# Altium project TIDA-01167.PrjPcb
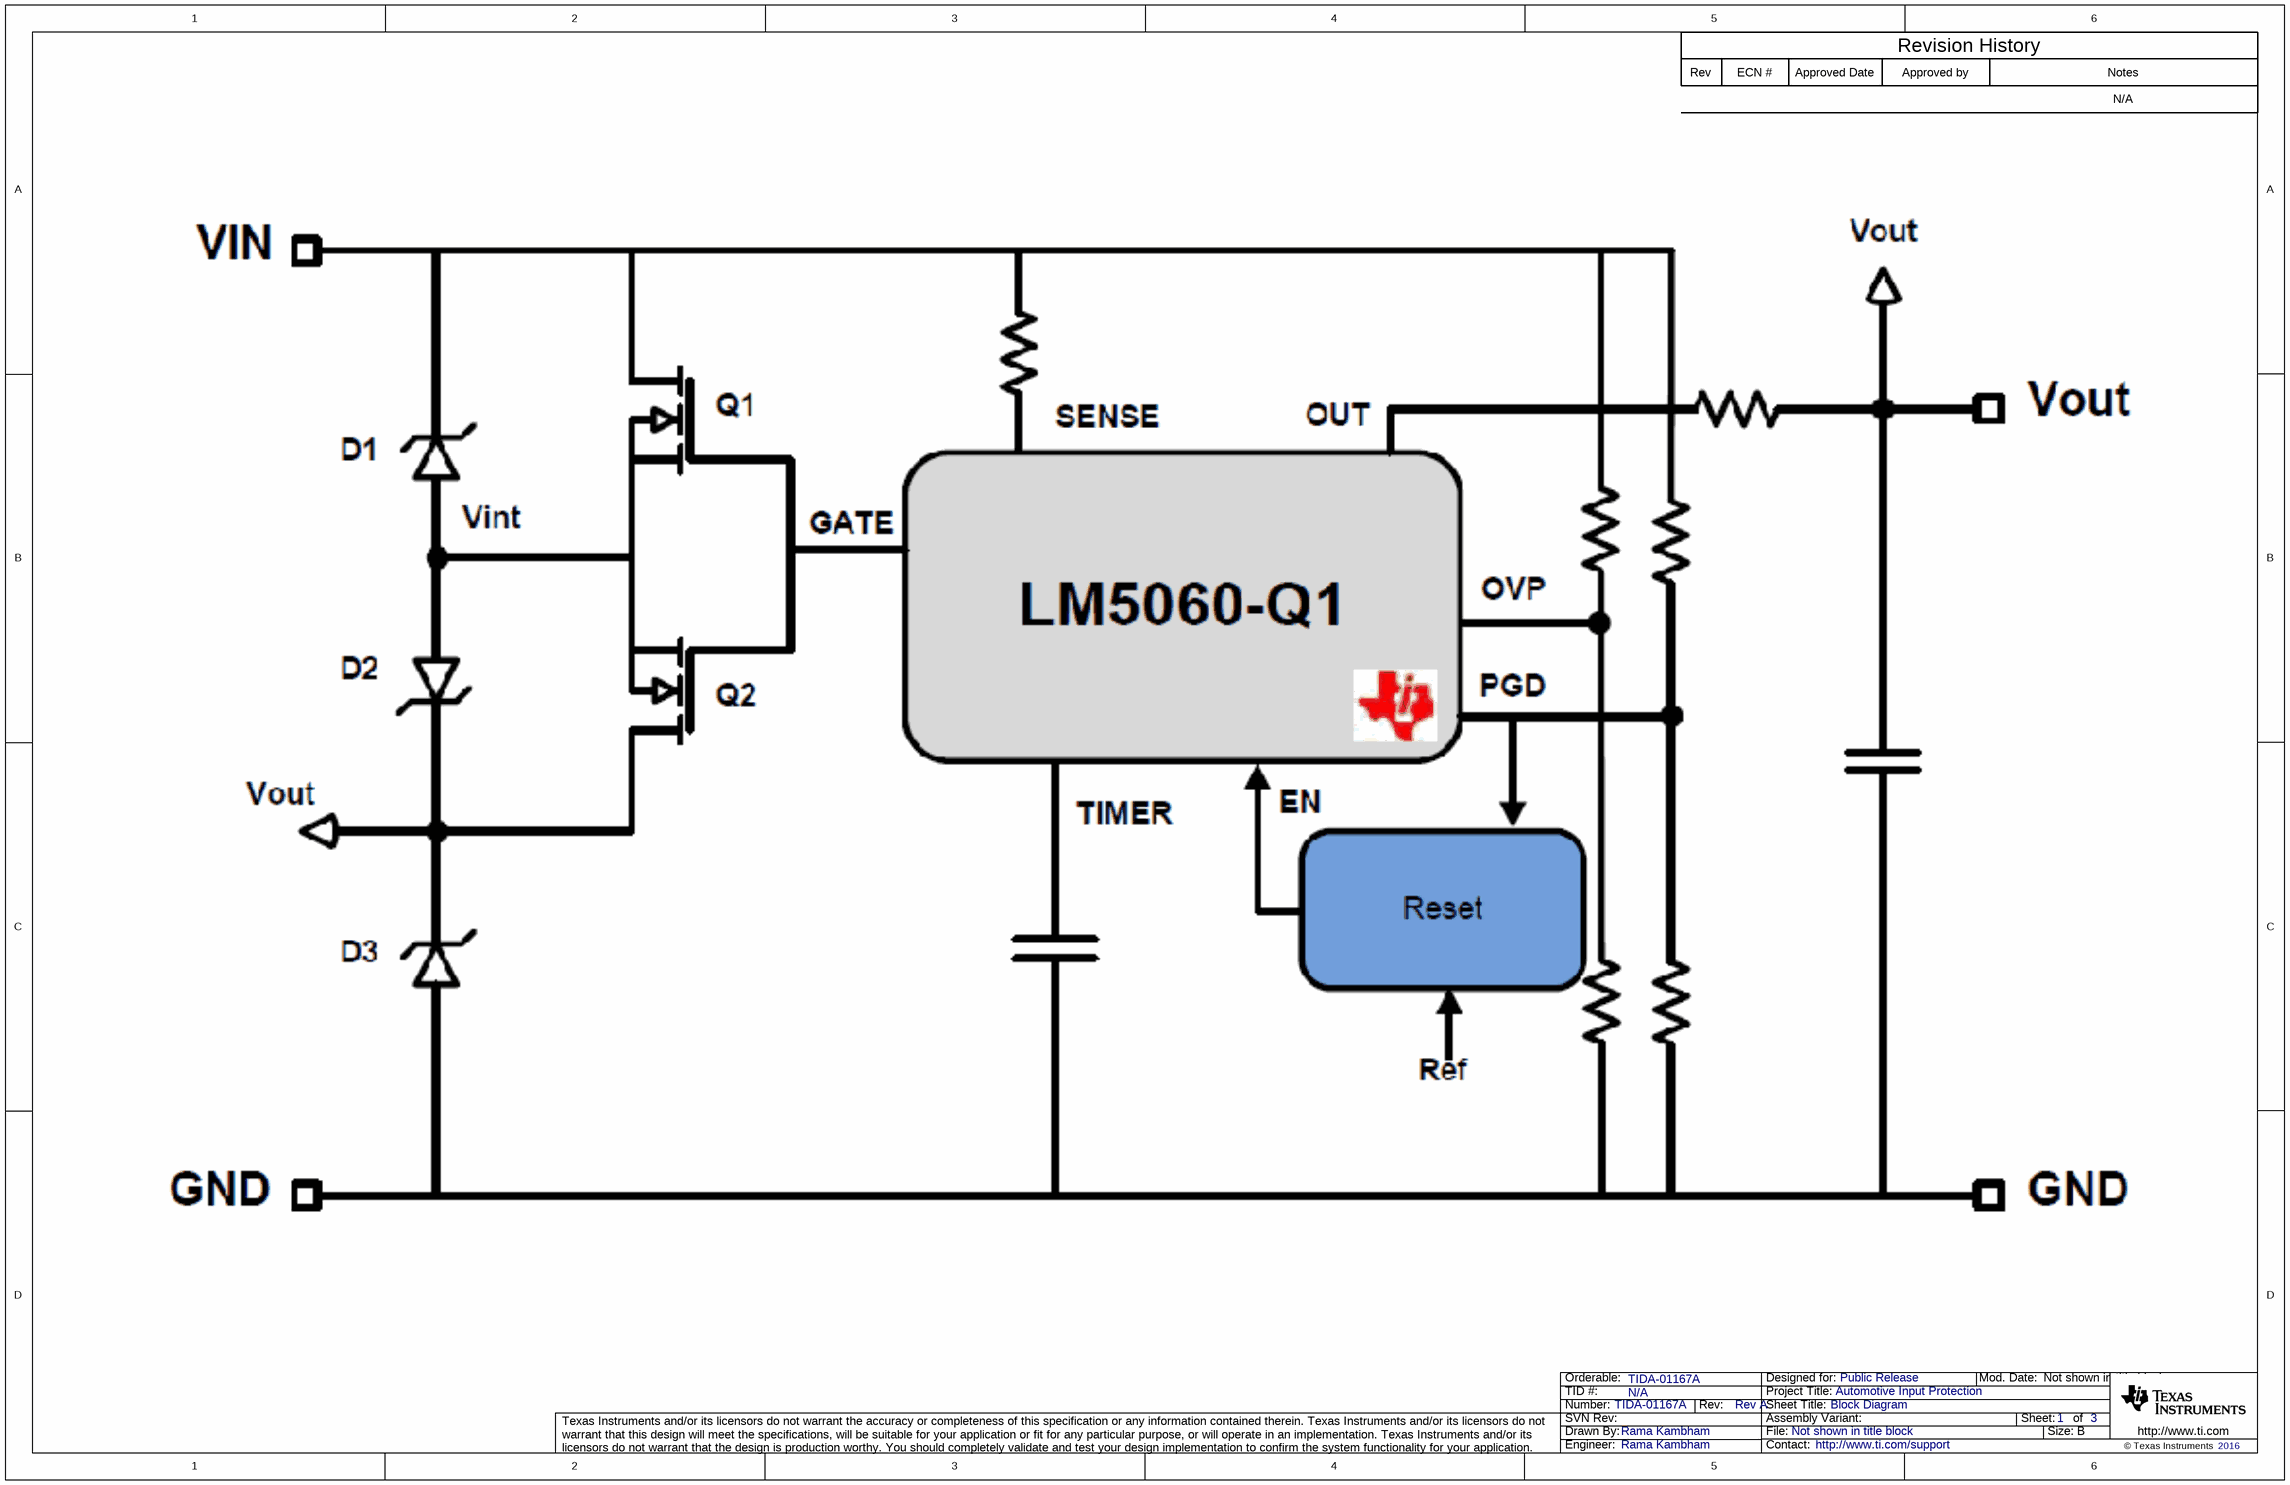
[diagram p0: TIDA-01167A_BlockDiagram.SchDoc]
CopyrightYear: 2016; EVM_orderable: TIDA-01167A; PCB_Layout: Rama Kambham; PCB_Rev: Rev A; PRJ_Customer: Public Release; PRJ_Engineer: Rama Kambham; PRJ_Number: TIDA-01167A; PRJ_Title: Automotive Input Protection; SCH_Rev: Rev A; TechSupport: http://www.ti.com/support; TID: N/A
3 sheets, 66 parts. Net scope: global (net labels, ports and power ports of the same name join across sheets).
Board file: TIDA-01167A_PCB.PcbDoc
Sheets:
  TIDA-01167A_BlockDiagram.SchDoc
  TIDA-01167A_AutomotiveInputProtection.SchDoc
  TIDA-01167A_Hardware.SchDoc

## Sheet TIDA-01167A_BlockDiagram.SchDoc: Block Diagram
size 431 x 279 mm; Date: Not shown in title block; ApprovedBy: Not shown in title block; CheckedBy: Not shown in title block; Author: Not shown in title block; CompanyName: Not shown in title block; DrawnBy: Rama Kambham; Engineer: Rama Kambham; Organization: Not shown in title block; Address1: Not shown in title block; Address2: Not shown in title block; Address3: Not shown in title block; Address4: Not shown in title block; DocumentNumber: 1; Revision: Use project parameter SCH_Rev; SheetNumber: 1; SheetTotal: 3; PageSetup: Record=PageOptions¦CenterHorizontal=True¦CenterVertical=True¦PrintScale=0.62¦XCorrection=1.00¦YCorrection=1.00¦PrintKind=0¦BorderSize=5000000¦LeftOffset=0¦BottomOffset=0¦Orientation=2¦PaperLength=1000¦PaperWidth=1000¦Scale=100¦PaperSource=15¦PrintQuality=600¦MediaType=1¦DitherType=10¦PrintScaleMode=1¦PaperKind=Letter

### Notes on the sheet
- Rev
- ECN #
- Approved Date
- Approved by
- Revision History
- Notes
- N/A

## Sheet TIDA-01167A_AutomotiveInputProtection.SchDoc: Schematic
size 431 x 279 mm; VersionControl_RevNumber: 1; Date: Not shown in title block; ApprovedBy: Not shown in title block; CheckedBy: Rama Kambham; Author: Rama Kambham; CompanyName: Not shown in title block; DrawnBy: Rama Kambham; Engineer: Rama Kambham; Organization: Not shown in title block; Address1: Not shown in title block; Address2: Not shown in title block; Address3: Not shown in title block; Address4: Not shown in title block; DocumentNumber: 1; Revision: Use project parameter SCH_Rev; SheetNumber: 2; SheetTotal: 3; PageSetup: Record=PageOptions¦CenterHorizontal=True¦CenterVertical=True¦PrintScale=0.64¦XCorrection=1.00¦YCorrection=1.00¦PrintKind=0¦BorderSize=5000000¦LeftOffset=0¦BottomOffset=0¦Orientation=2¦PaperLength=1000¦PaperWidth=1000¦Scale=100¦PaperSource=15¦PrintQuality=600¦MediaType=1¦DitherType=10¦PrintScaleMode=1¦PaperKind=8 1/2x11¦PaperIndex=1; EVM_orderable: TIDA-01167A
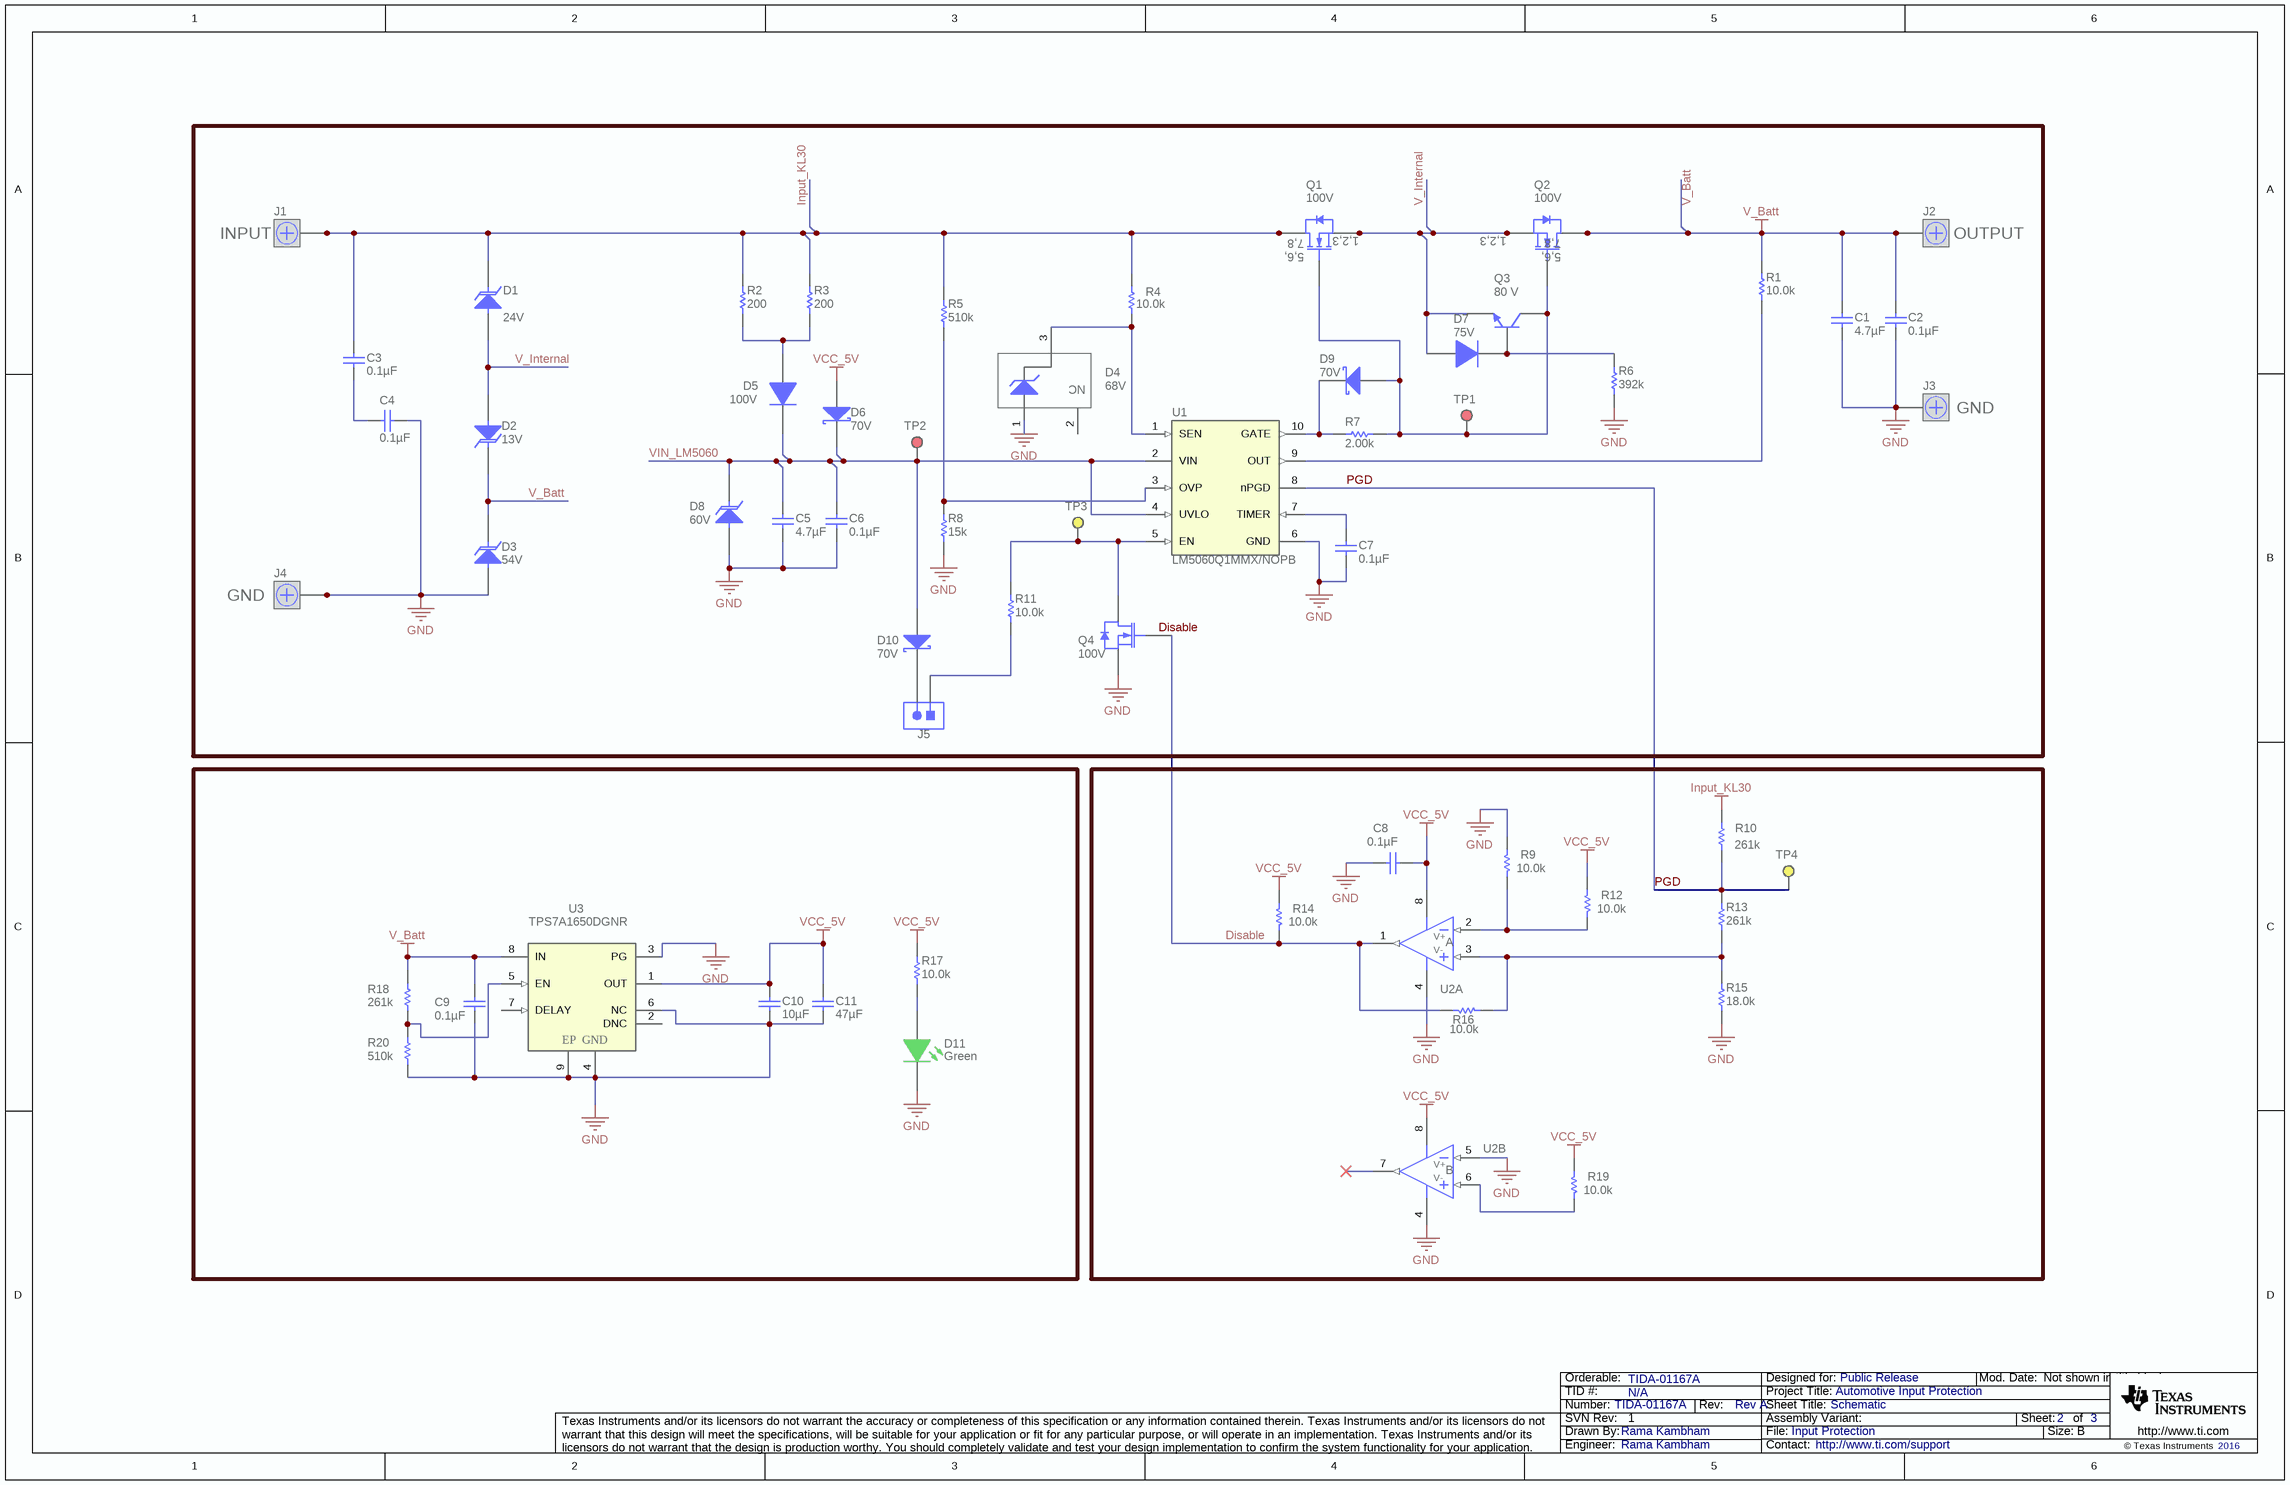
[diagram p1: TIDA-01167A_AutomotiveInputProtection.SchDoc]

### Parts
C1  ValueDisplayed: 4.7µF  [1210_270]  (hidden comment: GRM32ER71K475KE14L)
C2  ValueDisplayed: 0.1µF  [0603]  (hidden comment: GRM188R72A104KA35J)
C3  ValueDisplayed: 0.1µF  [1206]  (hidden comment: VJ1206Y104KBBAT4X)
C4  ValueDisplayed: 0.1µF  [1206]  (hidden comment: VJ1206Y104KBBAT4X)
C5  ValueDisplayed: 4.7µF  [1210_270L]  (hidden comment: GRM32ER71K475KE14L)
C6  ValueDisplayed: 0.1µF  [1206L]  (hidden comment: VJ1206Y104KBBAT4X)
C7  ValueDisplayed: 0.1µF  [0603S]  (hidden comment: GRM188R71H104KA93D)
C8  ValueDisplayed: 0.1µF  [0402]  (hidden comment: GRM155R71E104KE14D)
C9  ValueDisplayed: 0.1µF  [0603L]  (hidden comment: GRM188R72A104KA35J)
C10  ValueDisplayed: 10µF  [0805L]  (hidden comment: GRM219R61E106MA12)
C11  ValueDisplayed: 47µF  [1206_180]  (hidden comment: GRM31CR61A476KE15L)
D1  value 24V  [SMC]  (hidden comment: 5.0SMDJ24A)
D2  value 13V  [SOD-123W]  (hidden comment: PTVS13VS1UR,115)
D3  value 54V  [SMC]  (hidden comment: 5.0SMDJ54A)
D4  value 68V  [SOT-23L]  (hidden comment: BZX84C68LT1G)
D5  value 100V  [sod-323]  (hidden comment: BAS316,115)
D6  value 70V  [sod-323]  (hidden comment: 1N5711WS-7-F)
D7  value 75V  [sod-323]  (hidden comment: 1N4448WX-TP)
D8  value 60V  [SMA]  (hidden comment: SMAJ60A)
D9  value 70V  [SOD-323]  (hidden comment: BAS 170W E6327)
D10  value 70V  [sod-323]  (hidden comment: 1N5711WS-7-F)
D11  value Green  [LNJx37x8_Green]  (hidden comment: LNJ337W83RA)
J1  7693  [7693]  (value not drawn)
J2  7693  [7693]  (value not drawn)
J3  7693  [7693]  (value not drawn)
J4  7693  [7693]  (value not drawn)
J5  HTSW-102-07-G-S  [Samtec_HTSW-102-07-G-S]  (value not drawn)
Q1  value 100V  [TRANS_NexFET_Q5B]  (hidden comment: CSD19532Q5B)
Q2  value 100V  [TRANS_NexFET_Q5B]  (hidden comment: CSD19532Q5B)
Q3  value 80 V  [SOT-23]  (hidden comment: MMBTA06-7-F)
Q4  value 100V  [SOT-23L]  (hidden comment: BSS169H6327XTSA1)
R1  ValueDisplayed: 10.0k  [0402]  (hidden comment: CRCW040210K0FKED)
R2  ValueDisplayed: 200  [1206L]  (hidden comment: CRCW1206200RFKEA)
R3  ValueDisplayed: 200  [1206L]  (hidden comment: CRCW1206200RFKEA)
R4  ValueDisplayed: 10.0k  [0402S]  (hidden comment: CRCW040210K0FKED)
R5  ValueDisplayed: 510k  [0402S]  (hidden comment: CRCW0402510KJNED)
R6  ValueDisplayed: 392k  [0805_HV]  (hidden comment: CRCW0805392KFKEA)
R7  ValueDisplayed: 2.00k  [0402S]  (hidden comment: CRCW04022K00FKED)
R8  ValueDisplayed: 15k  [0402S]  (hidden comment: CRCW040215K0JNED)
R9  ValueDisplayed: 10.0k  [0402S]  (hidden comment: CRCW040210K0FKED)
R10  ValueDisplayed: 261k  [0402S]  (hidden comment: CRCW0402261KFKED)
R11  ValueDisplayed: 10.0k  [0402]  (hidden comment: CRCW040210K0FKED)
R12  ValueDisplayed: 10.0k  [0402S]  (hidden comment: CRCW040210K0FKED)
R13  ValueDisplayed: 261k  [0402S]  (hidden comment: CRCW0402261KFKED)
R14  ValueDisplayed: 10.0k  [0402S]  (hidden comment: CRCW040210K0FKED)
R15  ValueDisplayed: 18.0k  [0402S]  (hidden comment: CRCW040218K0FKED)
R16  ValueDisplayed: 10.0k  [0402S]  (hidden comment: CRCW040210K0FKED)
R17  ValueDisplayed: 10.0k  [0402]  (hidden comment: CRCW040210K0FKED)
R18  ValueDisplayed: 261k  [0402S]  (hidden comment: CRCW0402261KFKED)
R19  ValueDisplayed: 10.0k  [0402S]  (hidden comment: CRCW040210K0FKED)
R20  ValueDisplayed: 510k  [0402S]  (hidden comment: CRCW0402510KJNED)
TP1  5000  [Keystone5000]  (value not drawn)
TP2  5000  [Keystone5000]  (value not drawn)
TP3  5004  [Keystone5004]  (value not drawn)
TP4  5004  [Keystone5004]  (value not drawn)
U1  LM5060Q1MMX/NOPB  [MUB10A_L]
U2  LM2903AVQD  [D0008A_L]  (value not drawn)  (parts A,B of 2)
U3  TPS7A1650DGNR  [DGN0008C_L]

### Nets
GND: C1.2 C2.2 C4.1 C5.2 C6.2 C7.2 C8.1 C9.2 C10.2 C11.2 D3.2(A) D4.1(A) D8.2(A) D11.2(K) J3.1 J3.2 J3.3 J3.4 J4.1 J4.2 J4.3 J4.4 Q4.2(S) R6.1 R8.1 R9.2 R15.1 R20.1 U1.6(GND) U2.4(V-) U2.5(IN+) U3.3(PG) U3.4(GND) U3.6(NC) U3.9(EP)
Input_KL30: C3.1 D1.1(K) J1.1 J1.2 J1.3 J1.4 Q1.5(D) Q1.6(D) Q1.7(D) Q1.8(D) R2.2 R3.2 R4.1 R5.2 R10.2
V_Batt: C1.1 C2.1 C9.1 D2.1(K) D3.1(K) J2.1 J2.2 J2.3 J2.4 Q2.5(D) Q2.6(D) Q2.7(D) Q2.8(D) R1.1 R18.2 U3.8(IN)
VCC_5V: C8.2 C10.1 C11.1 D6.2(A) R12.1 R14.2 R17.1 R19.1 U2.8(V+) U3.1(OUT)
Disable: Q4.1(G) R14.1 R16.2 U2.1(OUT)
PGD: R10.1 R13.1 TP4.1 U1.8(nPGD)
V_Internal: D1.2(A) D2.2(A) D7.2(A) Q1.1(S) Q1.2(S) Q1.3(S) Q2.1(S) Q2.2(S) Q2.3(S) Q3.2(E)
VIN_LM5060: C5.1 C6.1 D5.1(K) D6.1(K) D8.1(K) D10.2(A) TP2.1 U1.2(VIN) U1.4(UVLO)
NetC3_2: C3.2 C4.2
NetC7_1: C7.1 U1.7(TIMER)
NetD4_3: D4.3(K) R4.2 U1.1(SEN)
NetD5_2: D5.2(A) R2.1 R3.1
NetD7_1: D7.1(K) Q3.1(B) R6.2
NetD9_1: D9.1(K) R7.1 U1.10(GATE)
NetD9_2: D9.2(A) Q1.4(G) Q2.4(G) Q3.3(C) R7.2 TP1.1
NetD10_1: D10.1(K) J5.2
NetD11_1: D11.1(A) R17.2
NetJ5_1: J5.1 R11.2
NetQ4_3: Q4.3(D) R11.1 TP3.1 U1.5(EN)
NetR1_2: R1.2 U1.9(OUT)
NetR5_1: R5.1 R8.2 U1.3(OVP)
NetR9_1: R9.1 R12.2 U2.2(IN-)
NetR13_2: R13.2 R15.2 R16.1 U2.3(IN+)
NetR18_1: R18.1 R20.2 U3.5(EN)
NetR19_2: R19.2 U2.6(IN-)

Not connected (* = marked no-connect by the designer): D4 2(NC); U2 7(OUT)*; U3 2(DNC) 7(DELAY)

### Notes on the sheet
- (near J1) INPUT
- (near J2) OUTPUT
- (near J3) GND
- (near J4) GND
- Labels drawn without touching a wire or pin: Disable, V_Batt

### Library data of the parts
C1 C5 = GRM32ER71K475KE14L: CAP, CERM, 4.7 µF, 80 V, +/- 10%, X7R, 1210; Manufacturer: MuRata; Polarized: N; CompType: Capacitor; Value: 4.7uF; U/M: EA; Cap_F: 0.0000047; Tolerance_%: 10; Value1: Unknown; VDC_V: 80; Value2: 80V; TaMin_C: -55; TaMax_C: 125; Cap_Case: 1210; AEC Category: Q200
C2 = GRM188R72A104KA35J: CAP, CERM, 0.1 µF, 100 V, +/- 10%, X7R, 0603; Manufacturer: MuRata; Polarized: N; CompType: Capacitor; Value: 0.1uF; U/M: EA; Cap_F: 0.0000001; Tolerance_%: 10; Value1: Unknown; VDC_V: 100; Value2: 100V; TaMin_C: -55; TaMax_C: 125; AEC Category: Q200
C3 C4 = VJ1206Y104KBBAT4X: CAP, CERM, 0.1 µF, 100 V, +/- 10%, X7R, 1206; Manufacturer: Vishay-Vitramon; Polarized: N; CompType: Capacitor; Value: 0.1uF; U/M: EA; Cap_F: 0.0000001; Tolerance_%: 10; Value1: Unknown; VDC_V: 100; Value2: 100V; TaMin_C: -55; TaMax_C: 125; AEC Category: Q200
C6 = VJ1206Y104KBBAT4X: CAP, CERM, 0.1 µF, 100 V, +/- 10%, X7R, 1206; Manufacturer: Vishay-Vitramon; Polarized: N; CompType: Capacitor; Value: 0.1uF; U/M: EA; Cap_F: 0.0000001; Tolerance_%: 10; Value1: Unknown; VDC_V: 100; Value2: 100V; TaMin_C: -55; TaMax_C: 125; Cap_Case: 1206; AEC Category: Q200
C7 = GRM188R71H104KA93D: CAP, CERM, 0.1 µF, 50 V, +/- 10%, X7R, 0603; Manufacturer: MuRata; Polarized: N; CompType: Capacitor; Value: 0.1uF; U/M: EA; Cap_F: 0.0000001; Tolerance_%: 10; Value1: Unknown; VDC_V: 50; Value2: 50V; TaMin_C: -55; TaMax_C: 125; Cap_Case: 0603; AEC Category: Q200
C8 = GRM155R71E104KE14D: CAP, CERM, 0.1 µF, 25 V, +/- 10%, X7R, 0402; Manufacturer: MuRata; Polarized: N; CompType: Capacitor; Value: 0.1uF; U/M: EA; Cap_F: 0.0000001; Tolerance_%: 10; Value1: Unknown; VDC_V: 25; Value2: 25V; TaMin_C: -55; TaMax_C: 125; AEC Category: Q200
C9 = GRM188R72A104KA35J: CAP, CERM, 0.1 µF, 100 V, +/- 10%, X7R, 0603; Manufacturer: MuRata; Polarized: N; CompType: Capacitor; Value: 0.1uF; U/M: EA; Cap_F: 0.0000001; Tolerance_%: 10; Value1: Unknown; VDC_V: 100; Value2: 100V; TaMin_C: -55; TaMax_C: 125; Cap_Case: 0603; AEC Category: Q200
C10 = GRM219R61E106MA12: CAP, CERM, 10 µF, 25 V, +/- 20%, X5R, 0805; Manufacturer: MuRata; Polarized: N; CompType: Capacitor; Value: 10uF; U/M: EA; Cap_F: 0.00001; Tolerance_%: 20; Value1: Unknown; VDC_V: 25; Value2: 25V; TaMin_C: -55; TaMax_C: 85; Cap_Case: 0805; AEC Category: Q200
C11 = GRM31CR61A476KE15L: CAP, CERM, 47 µF, 10 V, +/- 10%, X5R, 1206; Manufacturer: MuRata; Polarized: N; CompType: Capacitor; Value: 47uF; U/M: EA; Cap_F: 0.000047; Tolerance_%: 10; Value1: Unknown; Value2: 10V; TaMin_C: -55; TaMax_C: 85; Cap_Case: 1206; AEC Category: Q200
D1 = 5.0SMDJ24A: Diode, TVS, Uni, 24 V, 5000 W, SMC; Manufacturer: Littelfuse; U/M: EA; Power_W: 6.5; Vr_V: 24; Value1: 6.5W; RJA_CperW: 75; AEC Category: Q101
D2 = PTVS13VS1UR,115: Diode, TVS, Uni, 13 V,  W, SOD-123W; Manufacturer: NXP Semiconductor; U/M: EA; Power_W: 400; Vr_V: 13; Value1: 400W; RJA_CperW: 220; AEC Category: Q101
D3 = 5.0SMDJ54A: Diode, TVS, Uni, 54 V, 5000 W, SMC; Manufacturer: Littelfuse; U/M: EA; Power_W: 6.5; Vr_V: 54; Value1: 6.5W; RJA_CperW: 75; SizeAreaWB_mm2: 83.2686; SizeArea_mm2: 50.5686; SizeX_mm: 8.13; SizeY_mm: 6.22; SizeZ_mm: 2.6; AEC Category: Q101
D4 = BZX84C68LT1G: Diode, Zener, 68 V, 225 mW, SOT-23; Manufacturer: ON Semiconductor; U/M: EA; Power_W: 0.225; Vz_V: 68; Value1: 0.225W; RJA_CperW: 500; AEC Category: Q101; AEC Qualified: N
D5 = BAS316,115: Diode, Ultrafast, 100 V, 0.25 A, SOD-323; Manufacturer: NXP Semiconductor; U/M: EA; Vf_V: 1.4; Value1: 0.25A; Value2: 1.4V; Io_A: 0.25; Vr_V: 100; TJmax_C: 150; AEC Category: Q101
D6 D10 = 1N5711WS-7-F: Diode, Schottky, 70 V, 0.015 A, SOD-323; Manufacturer: Diodes Inc.; U/M: EA; Vf_V: 0.8; Value1: 0.015A; Value2: 0.8V; Io_A: 0.015; Vr_V: 70; AEC Category: Q101
D7 = 1N4448WX-TP: Diode, Switching, 75 V, 0.25 A, SOD-323; Manufacturer: Micro Commercial Components; U/M: EA; Value1: 0.25A; Io_A: 0.25; Vr_V: 75; TJmax_C: 150; AEC Category: Q101
D8 = SMAJ60A: Diode, TVS, Uni, 60 V, 400 W, SMA; Manufacturer: Littelfuse; U/M: EA; Power_W: 400; Vr_V: 60; Value1: 400W; RJA_CperW: 30; AEC Category: Q101
D9 = BAS 170W E6327: Diode, Schottky, 70 V, 0.07 A, AEC-Q101, SOD-323; Manufacturer: Infineon Technologies; U/M: EA; Vf_V: 1; Value1: 0.07A; Value2: 1V; Io_A: 0.07; Vr_V: 70; TJmax_C: 150; AEC Category: Q101; AEC Qualified: Y
D11 = LNJ337W83RA: LED, Green, SMD; Manufacturer: Panasonic; SymbolCreator: Altium; Vf_V: 1.95; Value2: 1.95V; Io_A: 0.005; Vr_V: 4; Ir_A: 1e-005; Tjmax_C: 85; Value1: W; U/M: EA
J1-J4 = 7693: Terminal screw, vertical, snap-in; Manufacturer: Keystone; SymbolCreator: a0412235; CompType: Screw Terminal
J5 = HTSW-102-07-G-S: Header, 100mil, 2x1, Gold, TH; Manufacturer: Samtec; SymbolCreator: a0412235
Q1 Q2 = CSD19532Q5B: MOSFET, N-CH, 100 V, 17 A, SON 5x6mm; Manufacturer: Texas Instruments; Alternate Manufacturer: None; U/M: EA; ChType: N; VdsMax_V: 100; Value1: ? ohm; Value2: 48 nC; QgTyp_nC: 48; Vgs_V: 20; IdsMax_A: 17; AEC Category: Q101
Q3 = MMBTA06-7-F, Diodes Inc.: Transistor, NPN, 80 V, 0.5 A, SOT-23; CompType: BJT; PNP: 0; NPN: 1; Vceo_V: 80; Vcesat1_V: 0.25; IcRated_A: 0.5; Value1: 0.5 A; TaMin_C: -55; TaMax_C: 150; U/M: EA; AEC Category: Q101
Q4 = BSS169H6327XTSA1: MOSFET, N-CH, 100 V, 0.17 A, SOT-23; Manufacturer: Infineon Technologies; Alternate Manufacturer: None; SymbolCreator: a0412235; U/M: EA; ChType: N; VdsMax_V: 100; Value1: ? ohm; Value2: 2.1 nC; QgTyp_nC: 2.1; Vgs_V: 20; IdsMax_A: 0.17; AEC Category: Q101
R1 R4 R9 R11 R12 R14 R16 R17 R19 = CRCW040210K0FKED: RES, 10.0 k, 1%, 0.063 W, 0402; Manufacturer: Vishay-Dale; CompType: Resistor; Value: 10.0k; Res_ohm: 10000; Value_Code: 10k0; Tolerance_%: 1; Power_W: 0.063; Value2: 0.063W; VDC_V: 50; TempCo: 100 ppm/C; EIA_Code: E96; U/M: EA; AEC Category: Q200
R2 R3 = CRCW1206200RFKEA: RES, 200, 1%, 0.25 W, 1206; Manufacturer: Vishay-Dale; CompType: Resistor; Value: 200; Value_Code: 200R; Tolerance_%: 1; Power_W: 0.25; Value2: 0.25W; TempCo: 100 ppm/C; EIA_Code: E96; U/M: EA; AEC Category: Q200
R5 R20 = CRCW0402510KJNED: RES, 510 k, 5%, 0.063 W, 0402; Manufacturer: Vishay-Dale; CompType: Resistor; Value: 510k; Res_ohm: 510000; Tolerance_%: 5; Power_W: 0.063; Value2: 0.063W; VDC_V: 50; TempCo: 200 ppm/C; EIA_Code: E24; U/M: EA; AEC Category: Q200
R6 = CRCW0805392KFKEA: RES, 392 k, 1%, 0.125 W, 0805; Manufacturer: Vishay-Dale; CompType: Resistor; Value: 392k; Res_ohm: 392000; Tolerance_%: 1; Power_W: 0.125; Value2: 0.125W; VDC_V: 150; TempCo: 100 ppm/C; EIA_Code: E96; U/M: EA; AEC Category: Q200
R7 = CRCW04022K00FKED: RES, 2.00 k, 1%, 0.063 W, 0402; Manufacturer: Vishay-Dale; CompType: Resistor; Value: 2.00k; Res_ohm: 2000; Value_Code: 2k00; Tolerance_%: 1; Power_W: 0.063; Value2: 0.063W; VDC_V: 50; TempCo: 100 ppm/C; EIA_Code: E96; U/M: EA; AEC Category: Q200
R8 = CRCW040215K0JNED: RES, 15 k, 5%, 0.063 W, 0402; Manufacturer: Vishay-Dale; CompType: Resistor; Value: 15k; Res_ohm: 15000; Value_Code: 15k0; Tolerance_%: 5; Power_W: 0.063; Value2: 0.063W; VDC_V: 50; TempCo: 200 ppm/C; EIA_Code: E24; U/M: EA; AEC Category: Q200
R10 R13 R18 = CRCW0402261KFKED: RES, 261 k, 1%, 0.063 W, 0402; Manufacturer: Vishay-Dale; CompType: Resistor; Value: 261k; Res_ohm: 261000; Tolerance_%: 1; Power_W: 0.063; Value2: 0.063W; VDC_V: 50; TempCo: 100 ppm/C; EIA_Code: E96; U/M: EA; AEC Category: Q200
R15 = CRCW040218K0FKED: RES, 18.0 k, 1%, 0.063 W, AEC-Q200 Grade 0, 0402; Manufacturer: Vishay-Dale; CompType: Resistor; Value: 18.0k; Res_ohm: 18000; Value_Code: 18k0; Tolerance_%: 1; Power_W: 0.063; Value2: 0.063W; VDC_V: 50; TempCo: 100 ppm/C; U/M: EA; AEC Category: Q200; AEC Qualified: Y; AEC Grade: 0
TP1 TP2 = 5000: Test Point, Miniature, Red, TH; Manufacturer: Keystone; CompType: Test Point Loop; ContactFinish: Silver
TP3 TP4 = 5004: Test Point, Miniature, Yellow, TH; Manufacturer: Keystone; CompType: Test Point Loop; ContactFinish: Silver
U1 = LM5060Q1MMX/NOPB: High-Side Protection Controller with Low Quiescent Current, 10-pin MSOP, Pb-Free; Manufacturer: Texas Instruments; PackageTopMarking: ZXTT*SZAB; PowerWise: N; CompType: Switcher
U2 = LM2903AVQD: Dual Comparator, D0008A; Manufacturer: Texas Instruments; CompType: OpAmp IC
U3 = TPS7A1650DGNR: Single Output LDO, 100 mA, Fixed 5 V Output, 3 to 60 V Input, with Enable and Power Good, 8-pin MSOP (DGN), -40 to 125 degC, Green (RoHS & no Sb/Br); Manufacturer: Texas Instruments; Alternate PartNumber: Equivalent; Accuracy(%): 2; Fixed Output Options(V): 5; Iout(Max)(A): 0.1; Iq(Typ)(mA): 0.004; Power Good: TRUE; Rating: Catalog; SubFamily: Single Channel LDO; Vdo(Typ)(mV): 60; Vin(Min)(V): 3

## Sheet TIDA-01167A_Hardware.SchDoc: Hardware Block Diagram
size 431 x 279 mm; Date: Not shown in title block; ApprovedBy: Not shown in title block; CheckedBy: Not shown in title block; Author: Not shown in title block; CompanyName: Not shown in title block; DrawnBy: Rama Kambham; Engineer: Not shown in title block; Organization: Not shown in title block; Address1: Not shown in title block; Address2: Not shown in title block; Address3: Not shown in title block; Address4: Not shown in title block; DocumentNumber: 1; Revision: Use project parameter SCH_Rev; SheetNumber: 3; SheetTotal: 3; PageSetup: Record=PageOptions¦CenterHorizontal=True¦CenterVertical=True¦PrintScale=1.00¦XCorrection=1.00¦YCorrection=1.00¦PrintKind=0¦BorderSize=5000000¦LeftOffset=0¦BottomOffset=0¦Orientation=2¦PaperLength=1000¦PaperWidth=1000¦Scale=100¦PaperSource=15¦PrintQuality=600¦MediaType=1¦DitherType=10¦PaperKind=Letter¦PrintScaleMode=1
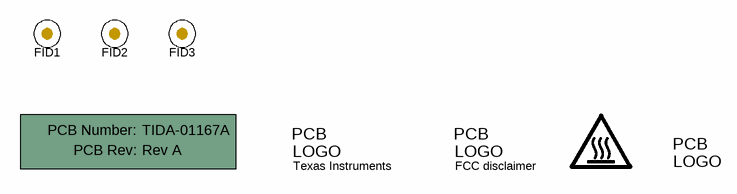
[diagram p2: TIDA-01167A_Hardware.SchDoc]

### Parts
!PCB1  Printed Circuit Board  (value not drawn)  (mechanical)
FID1  Fiducial  [Fiducial10-20]  (value not drawn)
FID2  Fiducial  [Fiducial10-20]  (value not drawn)
FID3  Fiducial  [Fiducial10-20]  (value not drawn)
Logo1  Texas Instruments  [TI_Stacked_SolderMask_Small]  (no BOM)
Logo2  FCC disclaimer  [FCC_disclaimer_stacked]  (no BOM)
LOGO4  CAUTION HOT SURFACE  [IEC_HotSurface_Small]  (value not drawn)  (no BOM)
Logo5  EU RoHS Exempt Logo  [EURoHS_Exempt_60mil_Stacked]  (value not drawn)  (no BOM)

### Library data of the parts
!PCB1 = PCB: Manufacturer: Any; PartNumber: TIDA-01167A; SymbolCreator: a0412235
FID1-FID3 = Fiducial: Fiducial mark.  There is nothing to buy or mount.; SymbolCreator: codlsc
Logo1 = TI_Logo: Texas Instrument Corporate Signature; SymbolCreator: codlsc
Logo2 = FCC_disclaimer: SymbolCreator: codlsc
LOGO4 = IEC_HotSurface: IEC 61010-1 Hot Surface Warning; SymbolCreator: a0412235
Logo5 = EURoHS_Exempt: SymbolCreator: a0412235

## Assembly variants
001: not fitted FID1 FID2 FID3 R16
